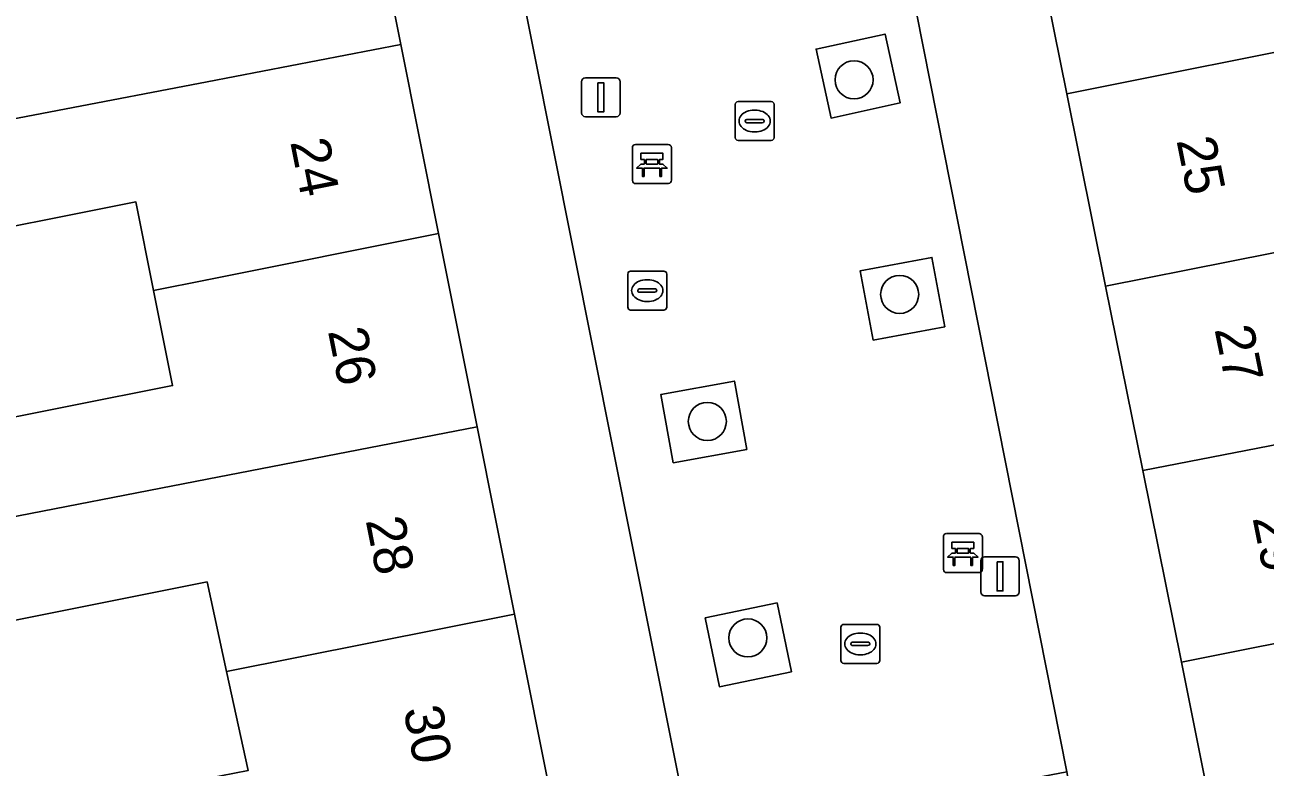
# Model space of a CAD drawing. Extents: x 162250 to 162661, y 380743 to 381606.
# Drawn here: x 162495.32 to 162527.18, y 381041.34 to 381060.4 of the extents above; entities that cross this region are included whole.
import ezdxf

# ---------------------------------------------------------------- set-up
doc = ezdxf.new("R2010")
doc.units = 0
for name, color, linetype in [('IMGEO_Bank', 7, 'Continuous'), ('IMGEO_Boom', 7, 'Continuous'), ('IMGEO_Brandkraan', 7, 'Continuous'), ('IMGEO_Erf', 7, 'Continuous'), ('IMGEO_Groenvoorziening', 7, 'Continuous'), ('IMGEO_Kolk', 7, 'Continuous'), ('IMGEO_Lichtmast', 7, 'Continuous'), ('IMGEO_Pand', 7, 'Continuous'), ('IMGEO_Pand_nummerreeks', 7, 'Continuous'), ('IMGEO_Woonerf_open', 7, 'Continuous')]:
    doc.layers.add(name, color=color, linetype=linetype)

msp = doc.modelspace()

# ---------------------------------------------------------------- linework, layer by layer
at = {"layer": 'IMGEO_Bank'}
for p, q in [((162510.93, 381056.399), (162510.93, 381057.24)), ((162510.93, 381057.24), (162510.93, 381056.399)), ((162511.005, 381057.324), (162511.846, 381057.324)), ((162511.846, 381057.324), (162511.005, 381057.324)), ((162511.93, 381057.249), (162511.93, 381056.408)), ((162511.93, 381056.408), (162511.93, 381057.249)), ((162511.239, 381056.83), (162511.239, 381056.936)), ((162511.283, 381056.936), (162511.283, 381056.83)), ((162511.571, 381056.942), (162511.289, 381056.942)), ((162511.577, 381056.83), (162511.577, 381056.936)), ((162511.621, 381056.936), (162511.621, 381056.83)), ((162511.627, 381056.722), (162511.234, 381056.722)), ((162511.289, 381056.824), (162511.571, 381056.824)), ((162511.855, 381056.324), (162511.014, 381056.324)), ((162511.014, 381056.324), (162511.855, 381056.324)), ((162518.918, 381046.41), (162518.918, 381047.251)), ((162518.918, 381047.251), (162518.918, 381046.41)), ((162518.993, 381047.335), (162519.834, 381047.335)), ((162519.834, 381047.335), (162518.993, 381047.335)), ((162519.918, 381047.26), (162519.918, 381046.419)), ((162519.918, 381046.419), (162519.918, 381047.26)), ((162519.615, 381046.733), (162519.222, 381046.733)), ((162519.227, 381046.841), (162519.227, 381046.947)), ((162519.271, 381046.947), (162519.271, 381046.841)), ((162519.559, 381046.953), (162519.277, 381046.953)), ((162519.277, 381046.835), (162519.559, 381046.835)), ((162519.565, 381046.841), (162519.565, 381046.947)), ((162519.609, 381046.947), (162519.609, 381046.841)), ((162519.843, 381046.335), (162519.002, 381046.335)), ((162519.002, 381046.335), (162519.843, 381046.335))]:
    msp.add_line(p, q, dxfattribs=at)
for points in [[(162511.233, 381056.942), (162511.147, 381056.942), (162511.147, 381057.103), (162511.71, 381057.103), (162511.71, 381056.942), (162511.627, 381056.942)], [(162511.177, 381056.722), (162511.035, 381056.722), (162511.147, 381056.824), (162511.233, 381056.824)], [(162511.227, 381056.715), (162511.227, 381056.508), (162511.184, 381056.508), (162511.184, 381056.715)], [(162511.627, 381056.824), (162511.71, 381056.824), (162511.822, 381056.722), (162511.683, 381056.722)], [(162511.677, 381056.715), (162511.677, 381056.508), (162511.633, 381056.508), (162511.633, 381056.715)], [(162519.221, 381046.953), (162519.135, 381046.953), (162519.135, 381047.114), (162519.698, 381047.114), (162519.698, 381046.953), (162519.615, 381046.953)], [(162519.165, 381046.733), (162519.023, 381046.733), (162519.135, 381046.835), (162519.221, 381046.835)], [(162519.215, 381046.726), (162519.215, 381046.519), (162519.172, 381046.519), (162519.172, 381046.726)], [(162519.615, 381046.835), (162519.698, 381046.835), (162519.81, 381046.733), (162519.671, 381046.733)], [(162519.665, 381046.726), (162519.665, 381046.519), (162519.621, 381046.519), (162519.621, 381046.726)]]:
    msp.add_lwpolyline(points, dxfattribs=at)
for centre, radius, start, end in [((162511.008, 381057.246), 0.0779, 92.4484, 184.2845), ((162511.008, 381057.246), 0.0779, 92.4484, 184.2845), ((162511.852, 381057.246), 0.0779, 2.4484, 94.2845), ((162511.852, 381057.246), 0.0779, 2.4484, 94.2845), ((162511.232, 381056.935), 0.00671, 2.8957, 87.1043), ((162511.289, 381056.935), 0.00671, 92.8957, 177.1043), ((162511.571, 381056.935), 0.00671, 2.8957, 87.1043), ((162511.628, 381056.935), 0.00671, 92.8957, 177.1043), ((162511.177, 381056.715), 0.00671, 2.8957, 87.1043), ((162511.234, 381056.715), 0.00671, 92.8957, 177.1043), ((162511.232, 381056.831), 0.00671, 272.8957, 357.1043), ((162511.289, 381056.831), 0.00671, 182.8957, 267.1043), ((162511.571, 381056.831), 0.00671, 272.8957, 357.1043), ((162511.628, 381056.831), 0.00671, 182.8957, 267.1043), ((162511.626, 381056.715), 0.00671, 2.8957, 87.1043), ((162511.683, 381056.715), 0.00671, 92.8957, 177.1043), ((162511.008, 381056.402), 0.0779, 182.4484, 274.2845), ((162511.008, 381056.402), 0.0779, 182.4484, 274.2845), ((162511.852, 381056.402), 0.0779, 272.4484, 4.2845), ((162511.852, 381056.402), 0.0779, 272.4484, 4.2845), ((162518.996, 381047.257), 0.0779, 92.4484, 184.2845), ((162518.996, 381047.257), 0.0779, 92.4484, 184.2845), ((162519.84, 381047.257), 0.0779, 2.4484, 94.2845), ((162519.84, 381047.257), 0.0779, 2.4484, 94.2845), ((162519.165, 381046.726), 0.00671, 2.8957, 87.1043), ((162519.222, 381046.726), 0.00671, 92.8957, 177.1043), ((162519.22, 381046.946), 0.00671, 2.8957, 87.1043), ((162519.22, 381046.842), 0.00671, 272.8957, 357.1043), ((162519.277, 381046.946), 0.00671, 92.8957, 177.1043), ((162519.277, 381046.842), 0.00671, 182.8957, 267.1043), ((162519.559, 381046.946), 0.00671, 2.8957, 87.1043), ((162519.559, 381046.842), 0.00671, 272.8957, 357.1043), ((162519.616, 381046.946), 0.00671, 92.8957, 177.1043), ((162519.616, 381046.842), 0.00671, 182.8957, 267.1043), ((162519.614, 381046.726), 0.00671, 2.8957, 87.1043), ((162519.671, 381046.726), 0.00671, 92.8957, 177.1043), ((162518.996, 381046.413), 0.0779, 182.4484, 274.2845), ((162518.996, 381046.413), 0.0779, 182.4484, 274.2845), ((162519.84, 381046.413), 0.0779, 272.4484, 4.2845), ((162519.84, 381046.413), 0.0779, 272.4484, 4.2845)]:
    msp.add_arc(centre, radius, start, end, dxfattribs=at)
at = {"layer": 'IMGEO_Boom'}
for centre in [(162516.622, 381058.987), (162517.794, 381053.478), (162512.853, 381050.215), (162513.894, 381044.657)]:
    msp.add_circle(centre, 0.489, dxfattribs=at)
at = {"layer": 'IMGEO_Brandkraan'}
for p, q in [((162510.883, 381054.075), (162511.735, 381054.075)), ((162510.808, 381053.149), (162510.808, 381054.001)), ((162511.296, 381053.855), (162511.321, 381053.855)), ((162511.809, 381054.001), (162511.809, 381053.149)), ((162511.067, 381053.569), (162511.067, 381053.581)), ((162511.505, 381053.532), (162511.107, 381053.532)), ((162511.11, 381053.618), (162511.508, 381053.618)), ((162511.551, 381053.581), (162511.551, 381053.569)), ((162511.319, 381053.295), (162511.294, 381053.295)), ((162511.735, 381053.075), (162510.883, 381053.075))]:
    msp.add_line(p, q, dxfattribs=at)
for points in [[(162510.883, 381054.075), (162511.735, 381054.075)], [(162510.808, 381053.149), (162510.808, 381054.001)], [(162511.809, 381054.001), (162511.809, 381053.149)], [(162511.735, 381053.075), (162510.883, 381053.075)]]:
    msp.add_lwpolyline(points, dxfattribs=at)
for centre, radius, start, end in [((162510.885, 381053.999), 0.0765, 91.552, 178.448), ((162510.885, 381053.999), 0.0765, 91.552, 178.448), ((162511.733, 381053.999), 0.0765, 1.552, 88.448), ((162511.733, 381053.999), 0.0765, 1.552, 88.448), ((162511.107, 381053.578), 0.0403, 85.8775, 175.7526), ((162511.104, 381053.568), 0.0366, 178.938, 274.7102), ((162511.508, 381053.575), 0.043, 264.8664, 352.4533), ((162511.512, 381053.58), 0.0386, 1.7309, 96.639), ((162510.885, 381053.151), 0.0765, 181.552, 268.448), ((162510.885, 381053.151), 0.0765, 181.552, 268.448), ((162511.733, 381053.151), 0.0765, 271.552, 358.448), ((162511.733, 381053.151), 0.0765, 271.552, 358.448)]:
    msp.add_arc(centre, radius, start, end, dxfattribs=at)
for centre, major_axis, ratio, start_param, end_param in [((162511.295, 381053.575), (-0.387, 0.002), 0.722429, 4.712389, 7.853982), ((162511.32, 381053.575), (-0.39, 0.002), 0.717154, 1.570796, 4.712389)]:
    msp.add_ellipse(centre, major_axis=major_axis, ratio=ratio, start_param=start_param, end_param=end_param, dxfattribs=at)
at = {"layer": 'IMGEO_Erf'}
for points in [[(162504.062, 381064.51), (162504.982, 381059.893), (162505.95, 381055.037), (162506.938, 381050.081), (162507.897, 381045.266), (162508.906, 381040.207), (162509.87, 381035.369), (162510.222, 381035.435), (162511.18, 381030.628), (162512.159, 381025.715), (162512.229, 381025.365), (162511.923, 381025.305), (162512.836, 381020.726), (162513.809, 381015.841), (162514.797, 381010.889)], [(162517.527, 381064.258), (162522.087, 381041.214), (162522.143, 381040.929), (162529.31, 381005.466)], [(162527.714, 381028.978), (162526.67, 381034.16), (162525.676, 381039.09), (162526.015, 381039.158), (162525.032, 381044.035), (162524.041, 381048.952), (162523.086, 381053.69), (162522.091, 381058.627), (162521.099, 381063.551)], [(162520.3, 381000), (162512.477, 381039.235), (162507.87, 381062.342)], [(162493.776, 381050.073), (162499.115, 381051.137), (162498.627, 381053.581), (162498.174, 381055.854), (162492.84, 381054.791)], [(162501.057, 381041.255), (162500.501, 381043.798), (162500, 381046.093), (162494.776, 381045.056)]]:
    msp.add_lwpolyline(points, dxfattribs=at)
at = {"layer": 'IMGEO_Groenvoorziening'}
for points in [[(162517.418, 381060.162), (162515.646, 381059.775), (162516.032, 381058.006), (162517.804, 381058.393)], [(162517.111, 381052.302), (162518.953, 381052.646), (162518.621, 381054.425), (162516.779, 381054.081)], [(162513.548, 381051.251), (162511.662, 381050.911), (162511.978, 381049.156), (162513.864, 381049.496)], [(162514.647, 381045.555), (162512.799, 381045.172), (162513.165, 381043.404), (162515.013, 381043.787)]]:
    msp.add_lwpolyline(points, close=True, dxfattribs=at)
at = {"layer": 'IMGEO_Kolk'}
for p, q in [((162513.567, 381057.503), (162513.567, 381058.355)), ((162513.642, 381058.429), (162514.494, 381058.429)), ((162514.055, 381058.209), (162514.08, 381058.209)), ((162514.568, 381058.355), (162514.568, 381057.503)), ((162513.826, 381057.923), (162513.826, 381057.935)), ((162514.264, 381057.886), (162513.866, 381057.886)), ((162513.869, 381057.972), (162514.267, 381057.972)), ((162514.31, 381057.935), (162514.31, 381057.923)), ((162514.078, 381057.649), (162514.053, 381057.649)), ((162514.494, 381057.429), (162513.642, 381057.429)), ((162516.283, 381044.077), (162516.283, 381044.929)), ((162516.358, 381045.003), (162517.21, 381045.003)), ((162517.284, 381044.929), (162517.284, 381044.077)), ((162516.542, 381044.497), (162516.542, 381044.509)), ((162516.585, 381044.546), (162516.983, 381044.546)), ((162516.771, 381044.783), (162516.796, 381044.783)), ((162517.026, 381044.509), (162517.026, 381044.497)), ((162516.98, 381044.46), (162516.582, 381044.46)), ((162516.794, 381044.223), (162516.769, 381044.223)), ((162517.21, 381044.003), (162516.358, 381044.003))]:
    msp.add_line(p, q, dxfattribs=at)
for points in [[(162513.567, 381057.503), (162513.567, 381058.355)], [(162513.642, 381058.429), (162514.494, 381058.429)], [(162514.568, 381058.355), (162514.568, 381057.503)], [(162514.494, 381057.429), (162513.642, 381057.429)], [(162516.283, 381044.077), (162516.283, 381044.929)], [(162516.358, 381045.003), (162517.21, 381045.003)], [(162517.284, 381044.929), (162517.284, 381044.077)], [(162517.21, 381044.003), (162516.358, 381044.003)]]:
    msp.add_lwpolyline(points, dxfattribs=at)
for centre, radius, start, end in [((162513.644, 381058.353), 0.0765, 91.552, 178.448), ((162513.644, 381058.353), 0.0765, 91.552, 178.448), ((162514.492, 381058.353), 0.0765, 1.552, 88.448), ((162514.492, 381058.353), 0.0765, 1.552, 88.448), ((162513.866, 381057.932), 0.0403, 85.8775, 175.7526), ((162513.863, 381057.922), 0.0366, 178.938, 274.7102), ((162514.267, 381057.929), 0.043, 264.8664, 352.4533), ((162514.271, 381057.934), 0.0386, 1.7309, 96.639), ((162513.644, 381057.505), 0.0765, 181.552, 268.448), ((162513.644, 381057.505), 0.0765, 181.552, 268.448), ((162514.492, 381057.505), 0.0765, 271.552, 358.448), ((162514.492, 381057.505), 0.0765, 271.552, 358.448), ((162516.36, 381044.927), 0.0765, 91.552, 178.448), ((162516.36, 381044.927), 0.0765, 91.552, 178.448), ((162517.208, 381044.927), 0.0765, 1.552, 88.448), ((162517.208, 381044.927), 0.0765, 1.552, 88.448), ((162516.582, 381044.506), 0.0403, 85.8775, 175.7526), ((162516.579, 381044.496), 0.0366, 178.938, 274.7102), ((162516.983, 381044.503), 0.043, 264.8664, 352.4533), ((162516.987, 381044.508), 0.0386, 1.7309, 96.639), ((162516.36, 381044.079), 0.0765, 181.552, 268.448), ((162516.36, 381044.079), 0.0765, 181.552, 268.448), ((162517.208, 381044.079), 0.0765, 271.552, 358.448), ((162517.208, 381044.079), 0.0765, 271.552, 358.448)]:
    msp.add_arc(centre, radius, start, end, dxfattribs=at)
for centre, major_axis, ratio, start_param, end_param in [((162514.054, 381057.929), (-0.387, 0.002), 0.722429, 4.712389, 7.853982), ((162514.079, 381057.929), (-0.39, 0.002), 0.717154, 1.570796, 4.712389), ((162516.77, 381044.503), (-0.387, 0.002), 0.722429, 4.712389, 7.853982), ((162516.795, 381044.503), (-0.39, 0.002), 0.717154, 1.570796, 4.712389)]:
    msp.add_ellipse(centre, major_axis=major_axis, ratio=ratio, start_param=start_param, end_param=end_param, dxfattribs=at)
at = {"layer": 'IMGEO_Lichtmast'}
for p, q in [((162509.622, 381058.138), (162509.622, 381058.938)), ((162509.622, 381058.938), (162509.622, 381058.138)), ((162509.722, 381059.038), (162510.512, 381059.038)), ((162510.512, 381059.038), (162509.722, 381059.038)), ((162510.612, 381058.938), (162510.612, 381058.138)), ((162510.612, 381058.138), (162510.612, 381058.938)), ((162510.512, 381058.038), (162509.722, 381058.038)), ((162509.722, 381058.038), (162510.512, 381058.038)), ((162519.977, 381046.739), (162520.767, 381046.739)), ((162520.767, 381046.739), (162519.977, 381046.739)), ((162519.877, 381045.839), (162519.877, 381046.639)), ((162519.877, 381046.639), (162519.877, 381045.839)), ((162520.867, 381046.639), (162520.867, 381045.839)), ((162520.867, 381045.839), (162520.867, 381046.639)), ((162520.767, 381045.739), (162519.977, 381045.739)), ((162519.977, 381045.739), (162520.767, 381045.739))]:
    msp.add_line(p, q, dxfattribs=at)
for points in [[(162510.042, 381058.913), (162510.192, 381058.913), (162510.192, 381058.163), (162510.042, 381058.163), (162510.042, 381058.913)], [(162520.297, 381046.614), (162520.447, 381046.614), (162520.447, 381045.864), (162520.297, 381045.864), (162520.297, 381046.614)]]:
    msp.add_lwpolyline(points, dxfattribs=at)
for centre, start, end in [((162509.722, 381058.938), 90, 180), ((162509.722, 381058.938), 90, 180), ((162510.512, 381058.938), 0, 90), ((162510.512, 381058.938), 360, 90), ((162509.722, 381058.138), 180, 270), ((162509.722, 381058.138), 180, 270), ((162510.512, 381058.138), 270, 0), ((162510.512, 381058.138), 270, 0), ((162519.977, 381046.639), 90, 180), ((162519.977, 381046.639), 90, 180), ((162520.767, 381046.639), 0, 90), ((162520.767, 381046.639), 360, 90), ((162519.977, 381045.839), 180, 270), ((162519.977, 381045.839), 180, 270), ((162520.767, 381045.839), 270, 0), ((162520.767, 381045.839), 270, 0)]:
    msp.add_arc(centre, 0.1, start, end, dxfattribs=at)
at = {"layer": 'IMGEO_Pand'}
for points in [[(162533.831, 381066.093), (162521.099, 381063.551), (162522.091, 381058.627), (162529.461, 381060.096), (162528.958, 381062.595), (162534.318, 381063.675)], [(162504.062, 381064.51), (162504.398, 381064.577), (162504.321, 381064.962), (162500, 381064.109), (162496.987, 381063.514), (162496.648, 381063.447), (162492.266, 381062.582), (162492.778, 381060.013), (162491.836, 381059.825), (162492.307, 381057.464), (162500, 381058.938), (162504.982, 381059.893)], [(162523.086, 381053.69), (162535.858, 381056.219), (162535.352, 381058.728), (162529.956, 381057.641), (162529.461, 381060.096), (162522.091, 381058.627)], [(162492.307, 381057.464), (162492.84, 381054.791), (162498.174, 381055.854), (162498.627, 381053.581), (162500, 381053.854), (162505.95, 381055.037), (162504.982, 381059.893), (162500, 381058.938)], [(162523.086, 381053.69), (162524.041, 381048.952), (162531.403, 381050.381), (162530.929, 381052.733), (162536.341, 381053.823), (162535.858, 381056.219)], [(162494.265, 381047.618), (162500, 381048.733), (162506.938, 381050.081), (162505.95, 381055.037), (162500, 381053.854), (162498.627, 381053.581), (162499.115, 381051.137), (162493.776, 381050.073)], [(162537.344, 381048.728), (162537.305, 381048.919), (162531.916, 381047.833), (162531.403, 381050.381), (162524.041, 381048.952), (162525.032, 381044.035), (162537.778, 381046.575)], [(162494.265, 381047.618), (162494.776, 381045.056), (162500, 381046.093), (162500.501, 381043.798), (162507.897, 381045.266), (162506.938, 381050.081), (162500, 381048.733)], [(162526.015, 381039.158), (162533.155, 381040.449), (162533.409, 381040.5), (162532.911, 381042.97), (162538.286, 381044.053), (162537.778, 381046.575), (162525.032, 381044.035)], [(162496.209, 381037.814), (162500, 381038.529), (162508.906, 381040.207), (162507.897, 381045.266), (162500.501, 381043.798), (162501.057, 381041.255), (162500, 381041.044), (162495.735, 381040.195)]]:
    msp.add_lwpolyline(points, close=True, dxfattribs=at)
at = {"layer": 'IMGEO_Woonerf_open'}
for points in [[(162517.527, 381064.258), (162516.662, 381064.047), (162514.83, 381063.685), (162514.576, 381065.01), (162510.865, 381064.31), (162511.129, 381062.913), (162509.296, 381062.603), (162507.87, 381062.342), (162512.477, 381039.235), (162513.922, 381039.54), (162515.725, 381039.882), (162516.023, 381038.603), (162519.722, 381039.307), (162519.451, 381040.706), (162521.287, 381041.063), (162522.087, 381041.214)], [(162516.032, 381058.006), (162515.646, 381059.775), (162517.418, 381060.162), (162517.804, 381058.393)], [(162517.111, 381052.302), (162516.779, 381054.081), (162518.621, 381054.425), (162518.953, 381052.646)], [(162513.864, 381049.496), (162511.978, 381049.156), (162511.662, 381050.911), (162513.548, 381051.251)], [(162514.647, 381045.555), (162515.013, 381043.787), (162513.165, 381043.404), (162512.799, 381045.172)]]:
    msp.add_lwpolyline(points, close=True, dxfattribs=at)

# ---------------------------------------------------------------- texts
at = {"layer": 'IMGEO_Pand_nummerreeks'}
for s, rotation, p in [('24', 281.2717, (162502.135, 381057.394)), ('25', 281.3944, (162524.903, 381057.433)), ('26', 281.2717, (162503.103, 381052.537)), ('27', 281.3944, (162525.88, 381052.586)), ('28', 281.2717, (162504.072, 381047.677)), ('29', 281.3959, (162526.856, 381047.738)), ('30', 281.2717, (162505.04, 381042.82))]:
    msp.add_text(s, height=1, rotation=rotation, dxfattribs=at).set_placement(p)

doc.saveas('drawing.dxf')
